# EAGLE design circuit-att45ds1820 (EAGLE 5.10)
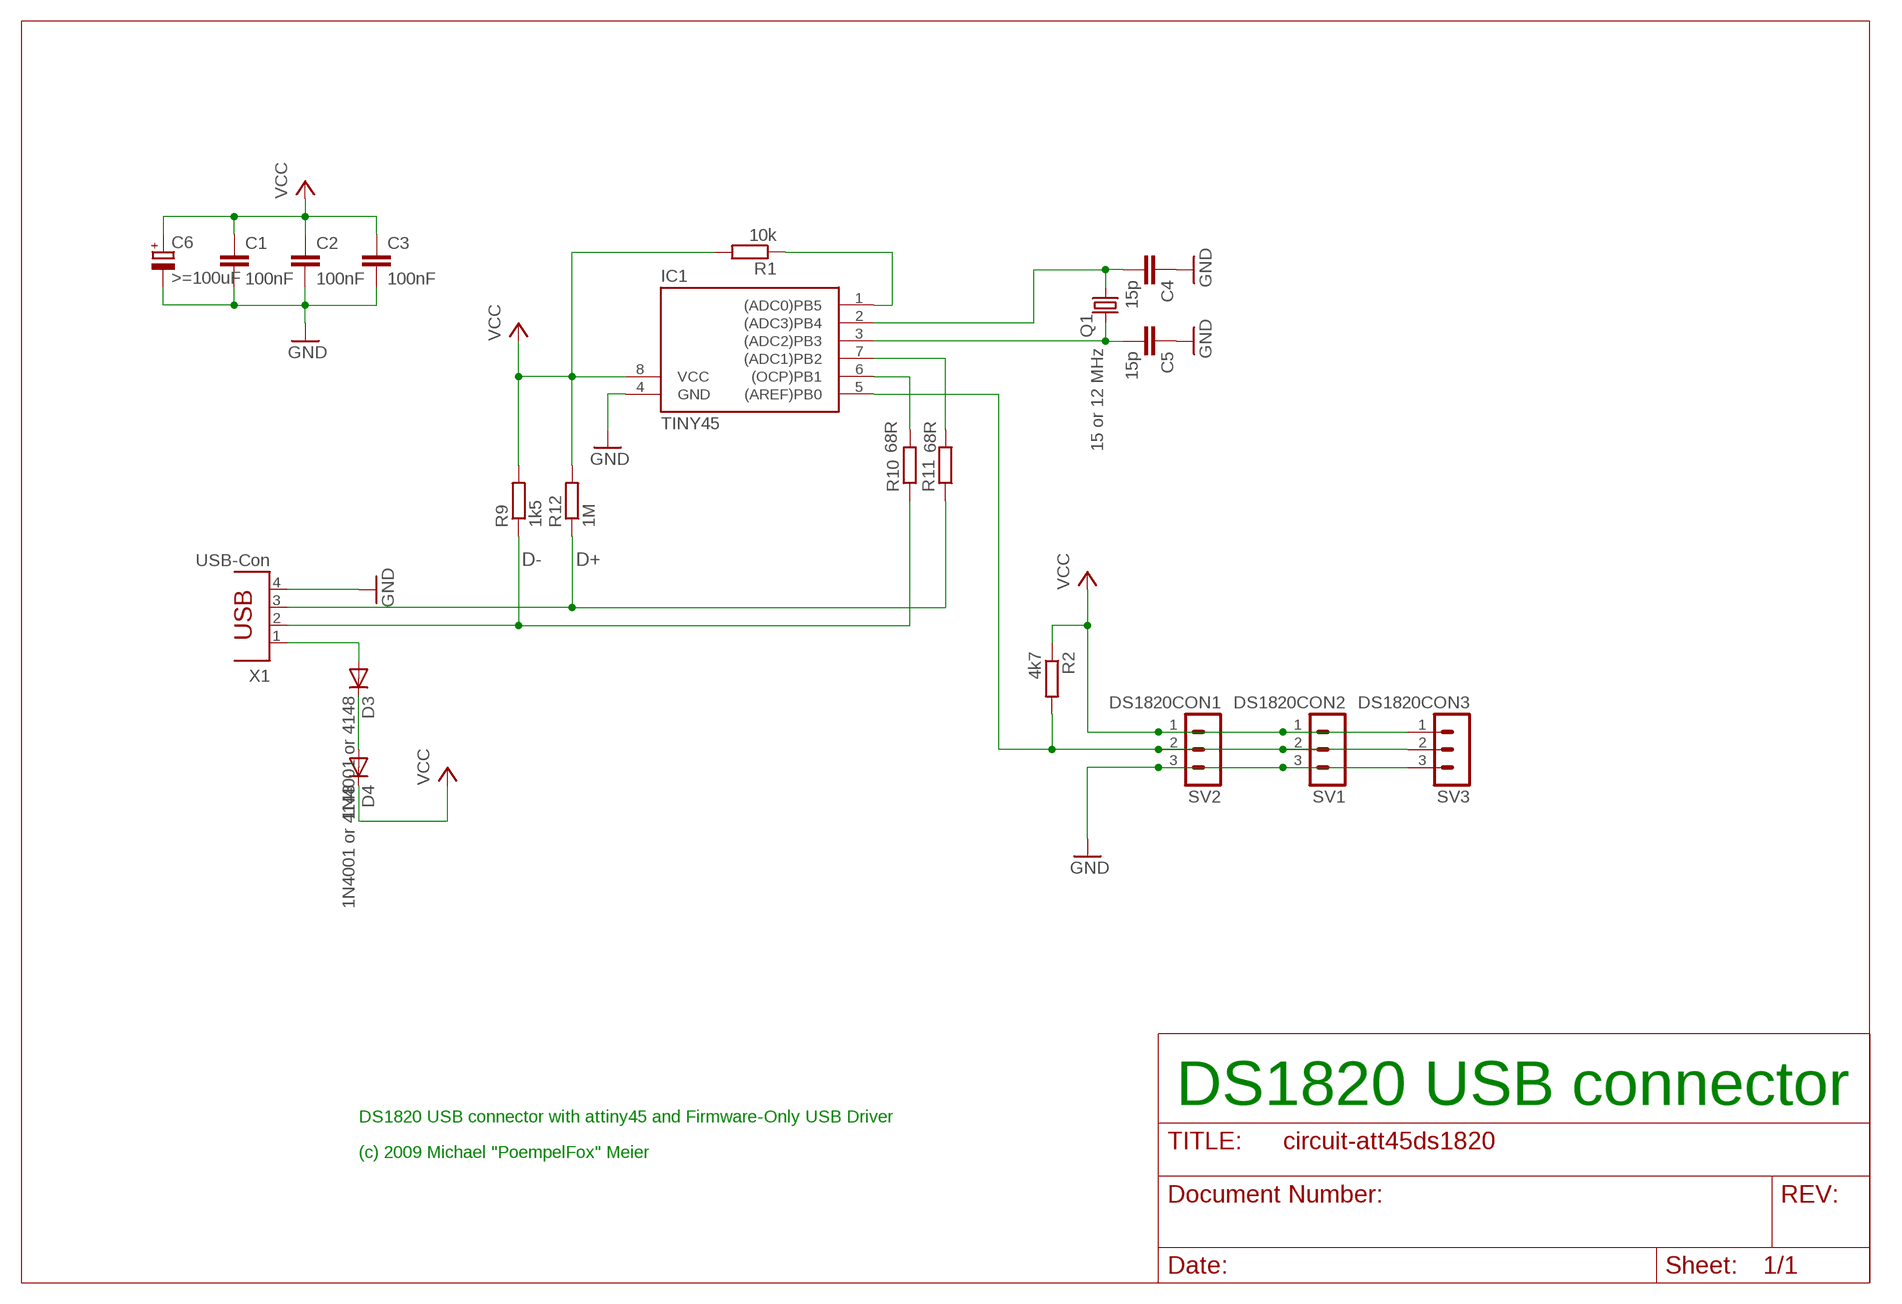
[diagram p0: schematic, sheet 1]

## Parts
C1  100nF  C-EU050-025X075  [C050-025X075]
C2  100nF  C-EU050-025X075  [C050-025X075]
C3  100nF  C-EU050-025X075  [C050-025X075]
C4  15p  C-EU025-025X050  [C025-025X050]
C5  15p  C-EU025-025X050  [C025-025X050]
C6  >=100uF  CPOL-EUE2.5-7  [E2,5-7]
D3  1N4001 or 4148  1N4004  [DO41-10]
D4  1N4001 or 4148  1N4004  [DO41-10]
IC1  TINY45  TINY15LP  [DIL08]
Q1  15 or 12 MHz  CRYTALHC49S  [HC49/S]
R1  10k  R-EU_0207/10  [0207/10]
R2  4k7  R-EU_0207/10  [0207/10]
R9  1k5  R-EU_0207/10  [0207/10]
R10  68R  R-EU_0207/10  [0207/10]
R11  68R  R-EU_0207/10  [0207/10]
R12  1M  R-EU_0207/10  [0207/10]
SV1  DS1820CON2  MA03-1  [MA03-1]
SV2  DS1820CON1  MA03-1  [MA03-1]
SV3  DS1820CON3  MA03-1  [MA03-1]
X1  USB-Con  PN61729  [PN61729]

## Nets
AVRD+: IC1.7((ADC1)PB2) R11.2
AVRD-: IC1.6((OCP)PB1) R10.2
AVRRESET: IC1.1((ADC0)PB5) R1.1
D+: R11.1 R12.1 X1.3
D-: R9.1 R10.1 X1.2
GND: C1.2 C2.2 C3.2 C4.1 C5.1 C6.- IC1.4(GND) SV1.3 SV2.3 SV3.3 X1.4
N$5: D3.A X1.1
N$6: D3.C D4.A
ONEWIRE: IC1.5((AREF)PB0) R2.2 SV1.2 SV2.2 SV3.2
VCC: C1.1 C2.1 C3.1 C6.+ D4.C IC1.8(VCC) R1.2 R2.1 R9.2 R12.2 SV1.1 SV2.1 SV3.1
XTAL1: C4.2 IC1.2((ADC3)PB4) Q1.1
XTAL2: C5.2 IC1.3((ADC2)PB3) Q1.2

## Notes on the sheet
- DS1820 USB connector
- DS1820 USB connector with attiny45 and Firmware-Only USB Driver
- (c) 2009 Michael "PoempelFox" Meier

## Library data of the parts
C1-C5 = rcl:C-EU: CAPACITOR, European symbol
C6 = rcl:CPOL-EU: POLARIZED CAPACITOR, European symbol
D3 D4 = diode:1N4004: DIODE
IC1 = avr-5:TINY15L: MICROCONTROLLER 2.7 V 1 Kbytes FLASH 64 bytes EEPROM 4-channel 10 bit ADC
Q1 = crystal:CRYTAL: CRYSTAL
R1 R2 R9-R12 = rcl:R-EU_: RESISTOR, European symbol
SV1-SV3 = con-lstb:MA03-1: PIN HEADER
X1 = con-berg:PN61729: BERG USB connector

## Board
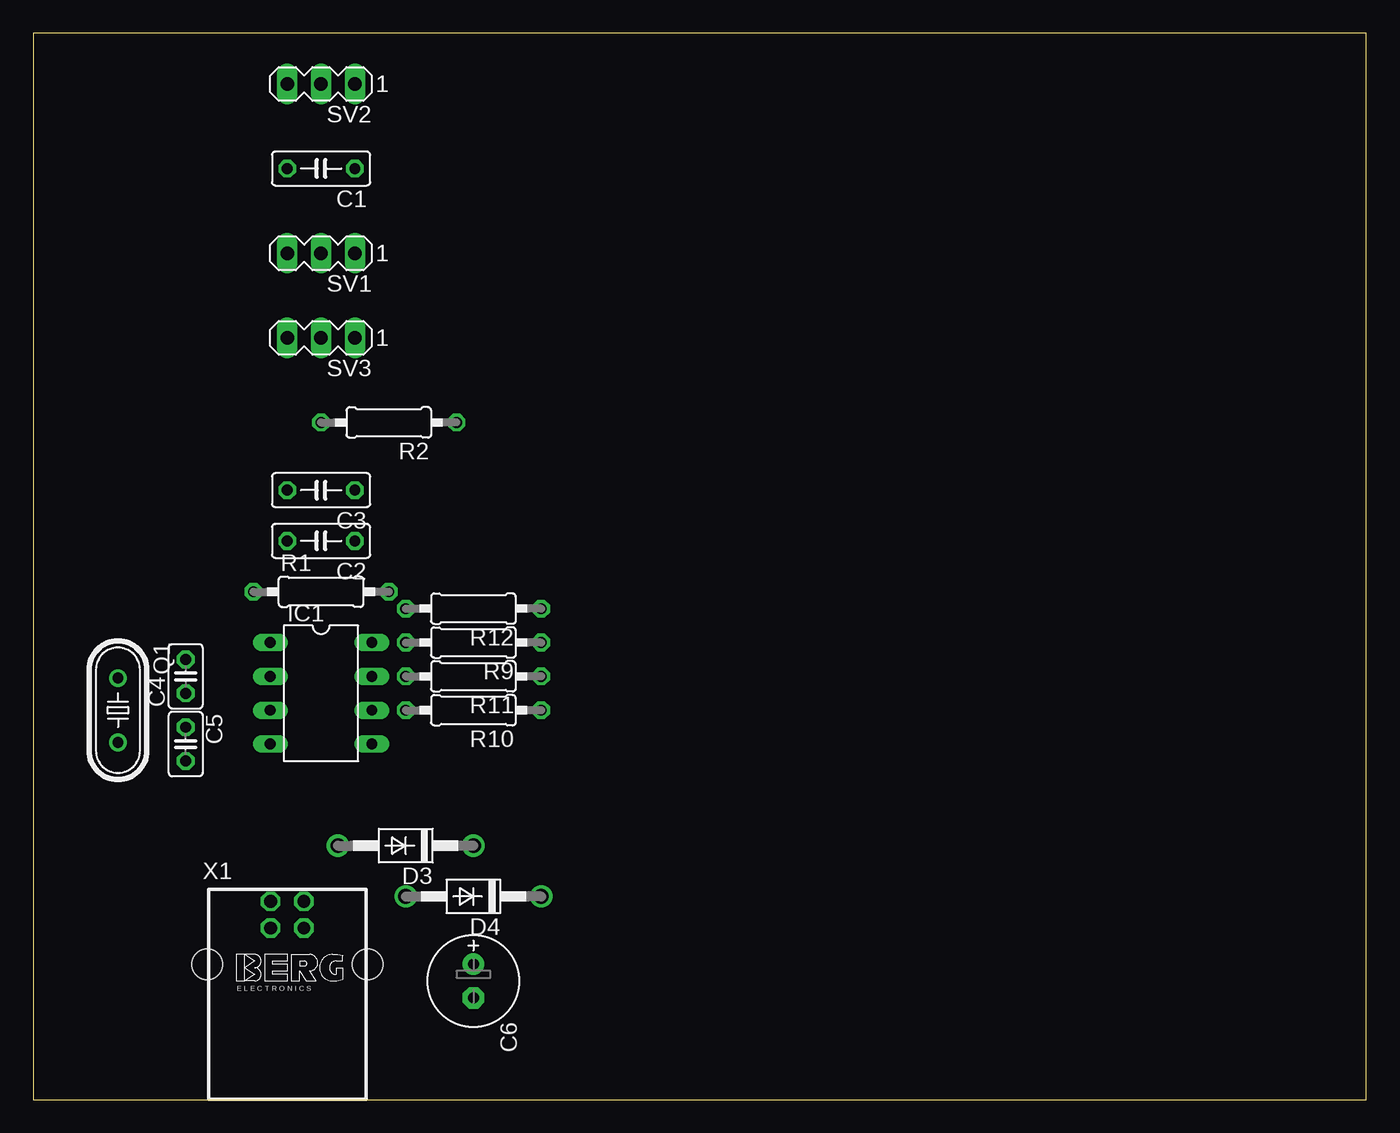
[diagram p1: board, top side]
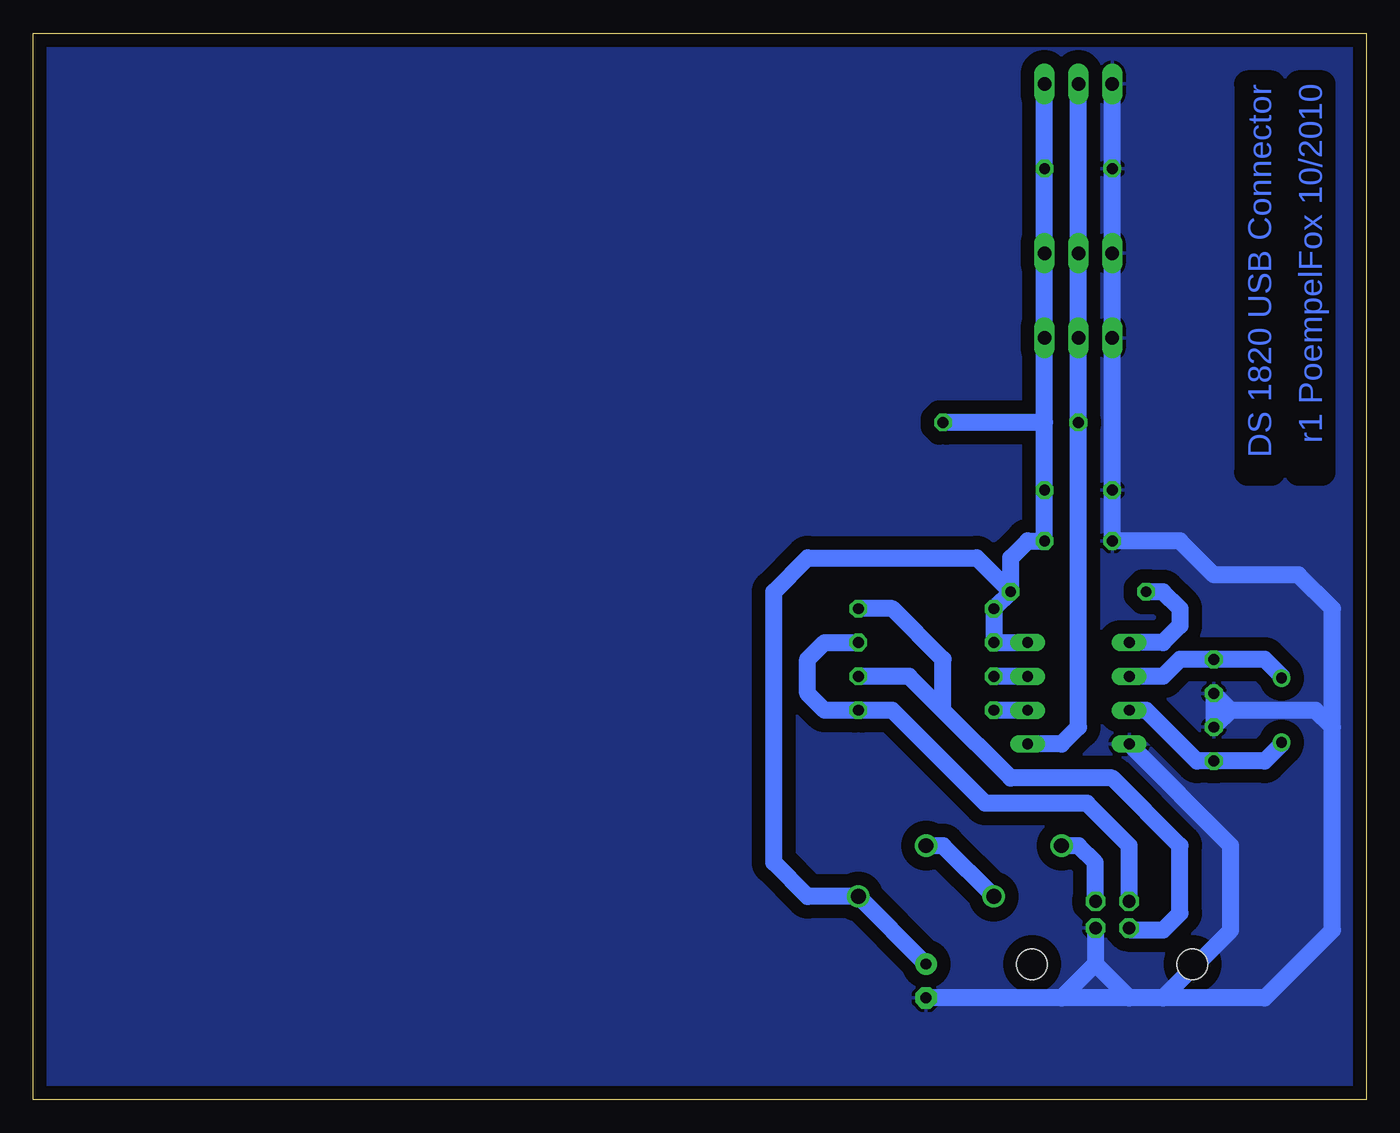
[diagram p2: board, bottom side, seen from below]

Size 100 x 80 mm. Coordinates in mm from the lower left corner, seen from the top.
Outline: 0,0 100,0 100,80 0,80 0,0
Copper layers (1*16): Top 0.035mm / dielectric 1.5mm / Bottom 0.035mm
Design rules "default": minimum track width 10mil, minimum drill 24mil, track to track 8mil, track to pad 8mil, pad to pad 8mil, via to via 8mil, smd to smd 8mil, copper to edge 40mil, drill to drill 8mil, minimum pad ring 10mil, minimum via ring 8mil, stop-mask expansion 4mil, vias tented up to drill 0mil, thermal gap 10mil

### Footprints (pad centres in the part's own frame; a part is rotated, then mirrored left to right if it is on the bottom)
C050-025X075 = drill 0.813 octagon: 1 -2.54,0; 2 2.54,0
C025-025X050 = drill 0.813 octagon: 1 -1.27,0; 2 1.27,0
E2,5-7 = drill 0.813 pad 1.6 round: + -1.27,0 | drill 0.813 pad 1.6 octagon: - 1.27,0
DO41-10 = drill 1.118 round: A 5.08,0; C -5.08,0
DIL08 = drill 0.813 long: 1 -3.81,-3.81; 2 -1.27,-3.81; 3 1.27,-3.81; 4 3.81,-3.81; 5 3.81,3.81; 6 1.27,3.81; 7 -1.27,3.81; 8 -3.81,3.81
HC49/S = drill 0.813 round: 1 -2.413,0; 2 2.413,0
0207/10 = drill 0.813 octagon: 1 -5.08,0; 2 5.08,0
MA03-1 = drill 1.016 long: 1 -2.54,0; 2 0,0; 3 2.54,0
PN61729 = drill 0.95 octagon: 1 1.25,4.71; 2 -1.25,4.71; 3 -1.25,2.71; 4 1.25,2.71 | hole 2.3: -6.02,0; 6.02,0

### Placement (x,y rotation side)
C1  21.59,69.85 180 top
C2  21.59,41.91 180 top
C3  21.59,45.72 180 top
C4  11.43,31.75 90 top
C5  11.43,26.67 270 top
C6  33.02,8.89 270 top
D3  27.94,19.05 180 top
D4  33.02,15.24 180 top
IC1  21.59,30.48 270 top
Q1  6.35,29.21 270 top
R1  21.59,38.1 0 top
R2  26.67,50.8 180 top
R9  33.02,34.29 180 top
R10  33.02,29.21 180 top
R11  33.02,31.75 180 top
R12  33.02,36.83 180 top
SV1  21.59,63.5 180 top
SV2  21.59,76.2 180 top
SV3  21.59,57.15 180 top
X1  19.05,10.16 0 top

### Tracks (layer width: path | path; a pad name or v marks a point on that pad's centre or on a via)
AVRD+
  Bottom 1.27: IC1.7 R11.2
AVRD-
  Bottom 1.27: IC1.6 R10.2
AVRRESET
  Bottom 1.27: IC1.1 15.24,34.29 13.97,35.56 13.97,36.83 15.24,38.1 R1.1
D+
  Bottom 1.27: R12.1 35.56,36.83 31.75,33.02 31.75,29.21 | R11.1 34.29,31.75 31.75,29.21 | X1.3 17.63,12.7 15.24,12.7 13.97,13.97 13.97,19.05 19.05,24.13 26.67,24.13 31.75,29.21
D-
  Bottom 0.813: X1.2 17.78,14.89
  Bottom 1.27: R9.1 40.64,34.29 41.91,33.02 41.91,30.48 40.64,29.21 R10.1 35.56,29.21 28.57,22.23 20.95,22.23 17.78,19.05 17.78,14.89
GND
  Bottom 1.27: 2.54,27.94 2.54,12.7 7.62,7.62 15.24,7.62 | 2.54,27.94 2.54,36.83 5.08,39.37 11.43,39.37 13.97,41.91 C2.2 C3.2 SV3.3 SV1.3 C1.2 SV2.3 | IC1.4 10.16,19.05 10.16,12.7 15.24,7.62 | 10.16,29.21 3.81,29.21 2.54,27.94 | 10.16,29.21 C4.1 C5.1 10.16,29.21 | 20.3,10.14 X1.4 | 17.78,7.62 20.3,10.14 | 15.24,7.62 17.78,7.62 | 17.78,7.62 22.86,7.62 | 22.86,7.62 C6.- | 20.3,10.14 20.34,10.14 22.86,7.62
  pour Bottom (isolate 1.016): 0,80.01 100.33,80.01 100.33,0 0,0
N$5
  Bottom 1.27: X1.1 20.32,14.89 20.32,17.78 21.59,19.05 D3.A
N$6
  Bottom 1.27: D3.C 31.75,19.05 D4.A
ONEWIRE
  Bottom 1.27: IC1.5 22.86,26.67 21.59,27.94 R2.2 SV3.2 SV1.2 SV2.2
VCC
  Bottom 1.27: IC1.8 R9.2 R12.2 R1.2 | R1.2 29.21,40.64 41.91,40.64 44.45,38.1 44.45,17.78 41.91,15.24 D4.C C6.+ | R1.2 26.67,40.64 25.4,41.91 C2.1 C3.1 24.13,50.8 | SV2.1 C1.1 SV1.1 SV3.1 24.13,50.8 | 24.13,50.8 R2.1
XTAL1
  Bottom 1.27: Q1.1 6.35,31.75 7.62,33.02 C4.2 13.97,33.02 15.24,31.75 IC1.2
XTAL2
  Bottom 1.27: Q1.2 6.35,26.67 7.62,25.4 C5.2 12.7,25.4 16.51,29.21 IC1.3

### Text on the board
Bottom: r1 PoempelFox 10/2010 | DS 1820 USB Connector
